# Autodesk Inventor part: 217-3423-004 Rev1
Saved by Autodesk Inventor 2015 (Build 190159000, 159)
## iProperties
Created: 2014-11
Part Number: 217-3423-004 Rev1
Material: Generic
Document SubType Name: Modeling
Designer: User
Density: 1 g/cm^3
Appearance: Default
Author: User
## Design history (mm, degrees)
node "217-3423-004 Rev1.ipt1"
node "Boss-Extrude1"
node "Base1"
